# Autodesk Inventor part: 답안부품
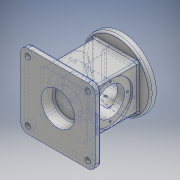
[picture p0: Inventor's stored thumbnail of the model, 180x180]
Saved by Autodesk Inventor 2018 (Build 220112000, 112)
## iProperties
Created: 2021-05
Part Number: 답안부품
Material: 알루미늄 6061
Document SubType Name: Modeling
Designer: theplan76
Density: 2.7 g/cm^3
Appearance: 알루미늄 - 평지
Mass: 1225.4 g
Surface Area: 907.661 cm^2
Volume: 453.851 cm^3
Author: theplan76
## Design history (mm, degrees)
sketch "스케치1"
  geometry: L1 (-37, 44)-(37, 44); L2 (37, 44)-(37, -44); L3 (37, -44)-(-37, -44); L4 (-37, -44)-(-37, 44); L5 (-37, 44)-(37, -44); L6 (37, 44)-(-37, -44); 1 further point
  constraints: 12 end point, 2 midpoint, 2 parallel, 1 horizontal, 1 perpendicular
  dimensions: "d0" = 74 distance of L1.start L1.end; "d1" = 88 distance of L1.end L2.end
extrude "돌출1" new body sketch "스케치1" stored distance "d2" = 74; taper "d3" = 0 deg
sketch "스케치2"
  geometry: C1 r 57.5 at (37, 37); 1 further point
  constraints: 1 centre point, 1 coincident
  dimensions: "d4" = 115 diameter of C1
extrude "돌출2" join sketch "스케치2" distance "d5" = 10; taper "d6" = 0 deg
sketch "스케치3"
  geometry: L1 (-25.5, 25.5)-(99.5, 25.5); L2 (99.5, 25.5)-(99.5, -99.5); L3 (99.5, -99.5)-(-25.5, -99.5); L4 (-25.5, -99.5)-(-25.5, 25.5); L5 (-25.5, 25.5)-(99.5, -99.5); L6 (99.5, 25.5)-(-25.5, -99.5); 1 further point
  constraints: 12 end point, 2 midpoint, 2 parallel, 1 horizontal, 1 perpendicular
  dimensions: "d7" = 125 distance of L1.start L1.end; "d8" = 125 distance of L1.end L2.end
extrude "돌출3" join sketch "스케치3" distance "d9" = 10; taper "d10" = 0 deg
sketch "스케치4"
  geometry: L1 (-26, 26)-(26, 26); L2 (26, 26)-(26, -26); L3 (26, -26)-(-26, -26); L4 (-26, -26)-(-26, 26); L5 (-26, 26)-(26, -26); L6 (26, 26)-(-26, -26); 1 further point
  constraints: 12 end point, 2 midpoint, 2 parallel, 1 horizontal, 1 perpendicular
  dimensions: "d11" = 52 distance of L1.start L1.end; "d12" = 52 distance of L1.end L2.end
extrude "돌출4" cut sketch "스케치4" distance "d13" = 8; taper "d14" = 0 deg
sketch "스케치5"
  geometry: L1 (-22, 22)-(22, 22); L2 (22, 22)-(22, -22); L3 (22, -22)-(-22, -22); L4 (-22, -22)-(-22, 22); L5 (-22, 22)-(22, -22); L6 (22, 22)-(-22, -22); 1 further point
  constraints: 12 end point, 2 midpoint, 2 parallel, 1 horizontal, 1 perpendicular
  dimensions: "d15" = 44 distance of L1.start L1.end; "d16" = 44 distance of L1.end L2.end
extrude "돌출5" cut sketch "스케치5" distance "d17" = 74; taper "d18" = 0 deg
sketch "스케치6"
  geometry: C1 r 28 at (37, -37); 1 further point
  constraints: 1 centre point, 1 coincident
  dimensions: "d19" = 56 diameter of C1
extrude "돌출6" cut sketch "스케치6" distance "d20" = 18; taper "d21" = -10 deg
sketch "스케치7"
  geometry: 1 further point
sketch "스케치8"
  geometry: C1 r 35 at (37, -44); 1 further point
  constraints: 1 centre point, 1 coincident
  dimensions: "d22" = 70 diameter of C1
extrude "돌출7" cut sketch "스케치8" distance "d23" = 3; taper "d24" = 0 deg
sketch "스케치9" dims "d25" = 58
  geometry: 3 further points
  constraints: 2 vertical alignment, 1 coincident, 2 other
hole "구멍1" sketch "스케치9" at (0, 29) diameter "d26" = 3.242; stored, may be unused: countersink angle "d30" = 90 deg, drill point angle "d32" = 118 deg; dims "d27" = 8, "d28" = 4, "d29" = 2, "d31" = 10
sketch "스케치10"
  geometry: C1 r 24 at (0, 0); 1 further point
  constraints: 1 centre point, 1 coincident
  dimensions: "d36" = 48 diameter of C1
extrude "돌출8" cut sketch "스케치10" extent not by distance; stored distance "d37" = 3; taper "d38" = 0 deg
sketch "스케치11"
  geometry: L1 (30, 33)-(-30, 33); L2 (-30, 33)-(-30, -33); L3 (-30, -33)-(30, -33); L4 (30, -33)-(30, 33); L5 (30, 33)-(-30, -33); L6 (-30, 33)-(30, -33); 4 further points
  constraints: 12 end point, 3 coincident, 2 midpoint, 2 parallel, 1 horizontal, 1 perpendicular
  dimensions: "d41" = 66 distance of L3.end L1.start; "d42" = 60 distance of L2.end L3.end
hole "구멍2" sketch "스케치11" at (30, 33), (30, -33), (-30, -33) diameter "d43" = 3.242; stored, may be unused: countersink angle "d47" = 90 deg, drill point angle "d49" = 118 deg; dims "d44" = 8, "d45" = 4, "d46" = 2, "d48" = 10
fillet "모깎기1" dims "d50" = 12
hole "구멍3" diameter "d53" = 9; stored, may be unused: countersink angle "d57" = 90 deg, drill point angle "d59" = 0 deg; dims "d51" = 10, "d52" = 10, "d54" = 8, "d55" = 4, "d56" = 2, "d58" = 10
fillet "모깎기2" dims "d60" = 3
sketch "스케치13"
  geometry: L1 (74, 0)-(74, 74) reference; L2 (74, 74)-(0, 74) reference; L3 (37, 74)-(37, 96.5); L4 (-13.5, 96.5)-(87.5, 96.5) reference; 2 further points
  constraints: 2 end point, 2 midpoint, 1 other
  dimensions: "d61" = 37 vertical distance of point (92, 37) L1.start; "d63" = 55 distance from line of point (92, 37) L3
feature "엠보싱1" sketch "스케치13" dims "d9" = 10, "d10" = 0, "d64" = 0.5, "d65" = 0
fillet "모깎기3" dims "d66" = 6
chamfer "모따기1" distance "d67" = 1; stored, may be unused: second distance "d68" = 2, angle "d69" = 45 deg
fillet "모깎기4" dims "d70" = 3
fillet "모깎기5" dims "d71" = 3
fillet "모깎기6" dims "d72" = 3
sketch "스케치15"
  geometry: L1 (50.5, -54)-(-50.5, -54) reference; L2 (37, -44)-(37, 44) reference; 3 further points
  dimensions: "d76" = 37 distance from line of point (0, -17) L1; "d77" = 43 distance of point (0, 26) point (0, -17); "d78" = 37 distance from line of point (0, -17) L2; "d79" = 37 distance from line of point (0, 26) L2
hole "구멍4" sketch "스케치15" at (0, -17), (0, 26) diameter "d80" = 4.134; stored, may be unused: countersink angle "d84" = 90 deg, drill point angle "d86" = 0 deg; dims "d81" = 10, "d82" = 4, "d83" = 2, "d85" = 24.95
fillet "모깎기7" dims "d87" = 3
fillet "모깎기8" dims "d88" = 3
fillet "모깎기9" dims "d89" = 3
fillet "모깎기10" dims "d90" = 3
node "솔리드1"
pattern_circular "원형 패턴1" dims angle "d34" = 360 deg
mirror "미러1"
mirror "미러2"
mirror "미러3"
mirror "미러4"
